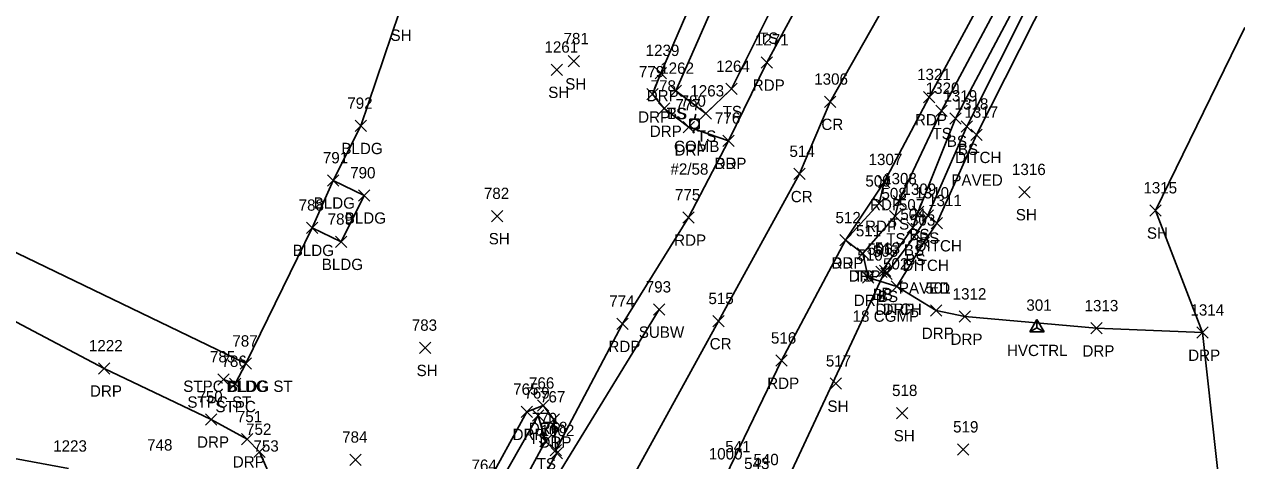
# Model space of a CAD drawing. Extents: x 1639430 to 1640195, y 612006 to 612917.
# Drawn here: x 1639766.2 to 1639980.2, y 612667.5 to 612744.6 of the extents above; entities that cross this region are included whole.
import ezdxf

# ---------------------------------------------------------------- set-up
doc = ezdxf.new("R2010")
doc.units = 0
for name, color, linetype in [('C_A', 7, 'Continuous'), ('C_I', 7, 'Continuous'), ('CPSM', 7, 'Continuous'), ('D_A', 7, 'Continuous'), ('D_C', 7, 'Continuous'), ('D_I', 7, 'Continuous'), ('D_TIC', 7, 'Continuous'), ('DCP', 7, 'Continuous'), ('DD', 7, 'Continuous'), ('L_A', 7, 'Continuous'), ('L_I', 7, 'Continuous'), ('L_TIC', 7, 'Continuous'), ('LABL', 7, 'Continuous'), ('LBC', 7, 'Continuous'), ('LBF', 7, 'Continuous'), ('LELB', 7, 'Continuous'), ('LSOGP', 7, 'Continuous'), ('P_A', 7, 'Continuous'), ('P_I', 7, 'Continuous'), ('P_TIC', 7, 'Continuous'), ('PET', 7, 'Continuous'), ('PRC', 7, 'Continuous'), ('R_A', 7, 'Continuous'), ('R_I', 7, 'Continuous'), ('R_TIC', 7, 'Continuous'), ('RDP', 7, 'Continuous'), ('U_A', 7, 'Continuous'), ('U_C', 7, 'Continuous'), ('U_I', 7, 'Continuous'), ('U_TIC', 7, 'Continuous'), ('UP', 7, 'Continuous'), ('UW', 7, 'Continuous')]:
    doc.layers.add(name, color=color, linetype=linetype)

msp = doc.modelspace()

# ---------------------------------------------------------------- linework, layer by layer
at = {"layer": 'CPSM'}
for p, q in [((1639943.69, 612690.31), (1639944.94, 612692.48)), ((1639943.69, 612690.31), (1639944.94, 612691.03)), ((1639946.19, 612690.31), (1639944.94, 612692.48)), ((1639944.94, 612691.03), (1639944.94, 612692.48)), ((1639944.94, 612691.03), (1639944.94, 612691.03)), ((1639944.94, 612691.03), (1639946.19, 612690.31)), ((1639943.69, 612690.31), (1639946.19, 612690.31))]:
    msp.add_line(p, q, dxfattribs=at)
at = {"layer": 'D_TIC'}
for points in [[(1639933.25, 612724.09), (1639935.25, 612726.09)], [(1639935.25, 612724.09), (1639933.25, 612726.09)], [(1639926.28, 612708.49), (1639928.28, 612710.49)], [(1639928.28, 612708.49), (1639926.28, 612710.49)], [(1639923.98, 612705.05), (1639925.98, 612707.05)], [(1639925.98, 612705.05), (1639923.98, 612707.05)], [(1639917.12, 612700.08), (1639919.12, 612702.08)], [(1639919.12, 612700.08), (1639917.12, 612702.08)], [(1639919.21, 612697.3), (1639921.21, 612699.3)], [(1639921.21, 612697.3), (1639919.21, 612699.3)]]:
    msp.add_lwpolyline(points, dxfattribs=at)
at = {"layer": 'DCP'}
msp.add_lwpolyline([(1639918.12, 612701.08), (1639877.22, 612613.44)], dxfattribs=at)
at = {"layer": 'DD'}
for points in [[(1639927.28, 612709.49), (1639934.25, 612725.09), (1639952.02, 612760.27), (1639969.9, 612794.69), (1639991.51, 612833.72), (1640000.55, 612849.98), (1639999.06, 612851.35), (1640004.27, 612861.49)], [(1639927.28, 612709.49), (1639924.98, 612706.05)], [(1639920.21, 612698.3), (1639924.98, 612706.05)]]:
    msp.add_lwpolyline(points, dxfattribs=at)
at = {"layer": 'L_TIC'}
for points in [[(1639859.2, 612735.58), (1639861.2, 612737.58)], [(1639861.2, 612735.58), (1639859.2, 612737.58)], [(1639862.19, 612737.07), (1639864.19, 612739.07)], [(1639864.19, 612737.07), (1639862.19, 612739.07)], [(1639880.2, 612731.85), (1639882.2, 612733.85)], [(1639882.2, 612731.85), (1639880.2, 612733.85)], [(1639880.2, 612731.85), (1639882.2, 612733.85)], [(1639882.2, 612731.85), (1639880.2, 612733.85)], [(1639890.05, 612732.19), (1639892.05, 612734.19)], [(1639892.05, 612732.19), (1639890.05, 612734.19)], [(1639885.51, 612727.85), (1639887.51, 612729.85)], [(1639887.51, 612727.85), (1639885.51, 612729.85)], [(1639927.08, 612728.31), (1639929.08, 612730.31)], [(1639929.08, 612728.31), (1639927.08, 612730.31)], [(1639929.58, 612726.96), (1639931.58, 612728.96)], [(1639931.58, 612726.96), (1639929.58, 612728.96)], [(1639824.6, 612725.67), (1639826.6, 612727.67)], [(1639826.6, 612725.67), (1639824.6, 612727.67)], [(1639931.54, 612725.53), (1639933.54, 612727.53)], [(1639933.54, 612725.53), (1639931.54, 612727.53)], [(1639819.71, 612716.04), (1639821.71, 612718.04)], [(1639821.71, 612716.04), (1639819.71, 612718.04)], [(1639825.19, 612713.39), (1639827.19, 612715.39)], [(1639827.19, 612713.39), (1639825.19, 612715.39)], [(1639919.56, 612712.35), (1639921.56, 612714.35)], [(1639921.56, 612712.35), (1639919.56, 612714.35)], [(1639941.71, 612713.98), (1639943.71, 612715.98)], [(1639943.71, 612713.98), (1639941.71, 612715.98)], [(1639848.7, 612709.75), (1639850.7, 612711.75)], [(1639850.7, 612709.75), (1639848.7, 612711.75)], [(1639922.98, 612710.48), (1639924.98, 612712.48)], [(1639924.98, 612710.48), (1639922.98, 612712.48)], [(1639924.69, 612709.85), (1639926.69, 612711.85)], [(1639926.69, 612709.85), (1639924.69, 612711.85)], [(1639964.85, 612710.74), (1639966.85, 612712.74)], [(1639966.85, 612710.74), (1639964.85, 612712.74)], [(1639816.01, 612707.68), (1639818.01, 612709.68)], [(1639818.01, 612707.68), (1639816.01, 612709.68)], [(1639918.93, 612709.72), (1639920.93, 612711.72)], [(1639920.93, 612709.72), (1639918.93, 612711.72)], [(1639922.01, 612707.73), (1639924.01, 612709.73)], [(1639924.01, 612707.73), (1639922.01, 612709.73)], [(1639922.27, 612706.07), (1639924.27, 612708.07)], [(1639924.27, 612706.07), (1639922.27, 612708.07)], [(1639821.14, 612705.21), (1639823.14, 612707.21)], [(1639823.14, 612705.21), (1639821.14, 612707.21)], [(1639913.21, 612703.16), (1639915.21, 612705.16)], [(1639915.21, 612703.16), (1639913.21, 612705.16)], [(1639916.5, 612699.9), (1639918.5, 612701.9)], [(1639918.5, 612699.9), (1639916.5, 612701.9)], [(1639917.41, 612699.56), (1639919.41, 612701.56)], [(1639919.41, 612699.56), (1639917.41, 612701.56)], [(1639835.97, 612686.49), (1639837.97, 612688.49)], [(1639837.97, 612686.49), (1639835.97, 612688.49)], [(1639804.32, 612683.7), (1639806.32, 612685.7)], [(1639806.32, 612683.7), (1639804.32, 612685.7)], [(1639804.32, 612683.7), (1639806.32, 612685.7)], [(1639806.32, 612683.7), (1639804.32, 612685.7)], [(1639800.36, 612680.91), (1639802.36, 612682.91)], [(1639802.36, 612680.91), (1639800.36, 612682.91)], [(1639802.45, 612680.12), (1639804.45, 612682.12)], [(1639804.45, 612680.12), (1639802.45, 612682.12)], [(1639908.47, 612680.18), (1639910.47, 612682.18)], [(1639910.47, 612680.18), (1639908.47, 612682.18)], [(1639855.89, 612674.52), (1639857.89, 612676.52)], [(1639857.89, 612674.52), (1639855.89, 612676.52)], [(1639855.89, 612674.52), (1639857.89, 612676.52)], [(1639857.89, 612674.52), (1639855.89, 612676.52)], [(1639920.17, 612674.97), (1639922.17, 612676.97)], [(1639922.17, 612674.97), (1639920.17, 612676.97)], [(1639857.23, 612670.01), (1639859.23, 612672.01)], [(1639859.23, 612670.01), (1639857.23, 612672.01)], [(1639930.94, 612668.54), (1639932.94, 612670.54)], [(1639932.94, 612668.54), (1639930.94, 612670.54)], [(1639823.68, 612666.74), (1639825.68, 612668.74)], [(1639825.68, 612666.74), (1639823.68, 612668.74)]]:
    msp.add_lwpolyline(points, dxfattribs=at)
at = {"layer": 'LABL'}
msp.add_lwpolyline([(1639710.2, 612699.83), (1639711.05, 612687.81), (1639724.43, 612679.59), (1639743.79, 612671.78), (1639774.03, 612666.16)], dxfattribs=at)
at = {"layer": 'LBC'}
for points in [[(1639805.32, 612684.7), (1639817.01, 612708.68), (1639822.14, 612706.21), (1639826.19, 612714.39), (1639820.71, 612717.04), (1639825.6, 612726.67)], [(1639736.37, 612717.97), (1639805.32, 612684.7)]]:
    msp.add_lwpolyline(points, dxfattribs=at)
at = {"layer": 'LBF'}
msp.add_lwpolyline([(1639801.36, 612681.91), (1639803.45, 612681.12), (1639805.32, 612684.7)], dxfattribs=at)
at = {"layer": 'LELB'}
for points in [[(1639881.2, 612732.85), (1639886.51, 612728.85), (1639891.05, 612733.19), (1639897.5, 612746.14), (1639910.14, 612769.99), (1639924.81, 612798.32), (1639936.89, 612820.09), (1639953.99, 612850.42), (1639966.82, 612870.89), (1639970.75, 612884.7)], [(1639920.56, 612713.35), (1639928.08, 612729.31), (1639945.96, 612762.85), (1639965.37, 612798.68), (1639987.12, 612835.84), (1639996.31, 612853.13)], [(1639923.98, 612711.48), (1639930.58, 612727.96), (1639948.36, 612761.64), (1639966.87, 612797.15), (1639988.64, 612835), (1639997.99, 612851.89)], [(1639925.69, 612710.85), (1639932.54, 612726.53), (1639949.92, 612761.12), (1639968.23, 612795.93), (1639988.64, 612835)], [(1639881.2, 612732.85), (1639890.04, 612752.99), (1639899.36, 612776.17), (1639909.23, 612806.8), (1639913.01, 612821.36), (1639914.66, 612832.24)], [(1639920.56, 612713.35), (1639919.93, 612710.72)], [(1639919.93, 612710.72), (1639914.21, 612704.16)], [(1639923.98, 612711.48), (1639923.01, 612708.73)], [(1639925.69, 612710.85), (1639923.27, 612707.07)], [(1639923.27, 612707.07), (1639918.41, 612700.56), (1639917.5, 612700.9), (1639923.01, 612708.73)], [(1639856.89, 612675.52), (1639839.34, 612644.57), (1639837.16, 612635.14)], [(1639856.89, 612675.52), (1639858.23, 612671.01), (1639843.5, 612643.86), (1639837.16, 612635.14)]]:
    msp.add_lwpolyline(points, dxfattribs=at)
at = {"layer": 'LSOGP'}
for points in [[(1639832.37, 612746.66), (1639825.6, 612726.67), (1639820.71, 612717.04), (1639817.01, 612708.68), (1639805.32, 612684.7), (1639736.37, 612717.97), (1639726.62, 612718.64), (1639725.22, 612708.89), (1639710.2, 612699.83), (1639687.52, 612693.83), (1639681.93, 612694.7), (1639686.17, 612669.71), (1639692.76, 612665.5), (1639691.76, 612656.22), (1639684.13, 612637.92), (1639678.27, 612630.17), (1639691.47, 612608.61), (1639716.65, 612607.37), (1639742.63, 612594.56), (1639733.8, 612554.66), (1639717.74, 612525.52)], [(1639984.07, 612643.4), (1639979.17, 612644.84), (1639974.14, 612690.17), (1639965.85, 612711.74), (1639981.6, 612744.05)]]:
    msp.add_lwpolyline(points, dxfattribs=at)
at = {"layer": 'P_TIC'}
for points in [[(1639896.29, 612736.85), (1639898.29, 612738.85)], [(1639898.29, 612736.85), (1639896.29, 612738.85)], [(1639907.46, 612729.93), (1639909.46, 612731.93)], [(1639909.46, 612729.93), (1639907.46, 612731.93)], [(1639924.91, 612730.74), (1639926.91, 612732.74)], [(1639926.91, 612730.74), (1639924.91, 612732.74)], [(1639889.53, 612723.04), (1639891.53, 612725.04)], [(1639891.53, 612723.04), (1639889.53, 612725.04)], [(1639902.06, 612717.18), (1639904.06, 612719.18)], [(1639904.06, 612717.18), (1639902.06, 612719.18)], [(1639917, 612715.74), (1639919, 612717.74)], [(1639919, 612715.74), (1639917, 612717.74)], [(1639916.11, 612711.94), (1639918.11, 612713.94)], [(1639918.11, 612711.94), (1639916.11, 612713.94)], [(1639882.42, 612709.49), (1639884.42, 612711.49)], [(1639884.42, 612709.49), (1639882.42, 612711.49)], [(1639910.17, 612705.47), (1639912.17, 612707.47)], [(1639912.17, 612705.47), (1639910.17, 612707.47)], [(1639870.82, 612690.73), (1639872.82, 612692.73)], [(1639872.82, 612690.73), (1639870.82, 612692.73)], [(1639887.75, 612691.2), (1639889.75, 612693.2)], [(1639889.75, 612691.2), (1639887.75, 612693.2)], [(1639898.84, 612684.23), (1639900.84, 612686.23)], [(1639900.84, 612684.23), (1639898.84, 612686.23)], [(1639859.03, 612668.42), (1639861.03, 612670.42)], [(1639861.03, 612668.42), (1639859.03, 612670.42)], [(1639859.19, 612667.9), (1639861.19, 612669.9)], [(1639861.19, 612667.9), (1639859.19, 612669.9)]]:
    msp.add_lwpolyline(points, dxfattribs=at)
at = {"layer": 'PET'}
for points in [[(1639897.29, 612737.85), (1639913.55, 612767.99), (1639928.75, 612795.82), (1639941.92, 612819.27), (1639957.68, 612846.96), (1639976.9, 612880.46)], [(1639918, 612716.74), (1639925.91, 612731.74), (1639943.29, 612763.86), (1639962.3, 612799.99), (1639983.33, 612836.7), (1639995.21, 612854.18), (1640002.09, 612863.22)], [(1639897.29, 612737.85), (1639890.53, 612724.04)], [(1639860.03, 612669.42), (1639871.82, 612691.73), (1639883.42, 612710.49), (1639890.53, 612724.04)], [(1639918, 612716.74), (1639911.17, 612706.47)], [(1639918, 612716.74), (1639917.11, 612712.94)], [(1639917.11, 612712.94), (1639911.17, 612706.47), (1639899.84, 612685.23)], [(1639899.84, 612685.23), (1639889.96, 612664.78)], [(1639860.03, 612669.42), (1639860.19, 612668.9)], [(1639860.19, 612668.9), (1639846.37, 612644.49), (1639830.05, 612614.56), (1639810.07, 612579.97), (1639792.17, 612548.77), (1639765.87, 612504.14)]]:
    msp.add_lwpolyline(points, dxfattribs=at)
at = {"layer": 'PRC'}
for points in [[(1639988.18, 612868.16), (1639972.03, 612846.35), (1639947.21, 612799.98), (1639926.52, 612762.8), (1639908.46, 612730.93)], [(1639908.46, 612730.93), (1639903.06, 612718.18)], [(1639903.06, 612718.18), (1639888.75, 612692.2)], [(1639888.75, 612692.2), (1639858.8, 612637.72)]]:
    msp.add_lwpolyline(points, dxfattribs=at)
at = {"layer": 'R_TIC'}
for points in [[(1639877.58, 612734.99), (1639879.58, 612736.99)], [(1639879.58, 612734.99), (1639877.58, 612736.99)], [(1639876.07, 612731.23), (1639878.07, 612733.23)], [(1639878.07, 612731.23), (1639876.07, 612733.23)], [(1639878.12, 612728.71), (1639880.12, 612730.71)], [(1639880.12, 612728.71), (1639878.12, 612730.71)], [(1639882.5, 612725.41), (1639884.5, 612727.41)], [(1639884.5, 612725.41), (1639882.5, 612727.41)], [(1639889.53, 612723.04), (1639891.53, 612725.04)], [(1639891.53, 612723.04), (1639889.53, 612725.04)], [(1639910.17, 612705.47), (1639912.17, 612707.47)], [(1639912.17, 612705.47), (1639910.17, 612707.47)], [(1639913.21, 612703.16), (1639915.21, 612705.16)], [(1639915.21, 612703.16), (1639913.21, 612705.16)], [(1639914.13, 612698.87), (1639916.13, 612700.87)], [(1639916.13, 612698.87), (1639914.13, 612700.87)], [(1639919.21, 612697.3), (1639921.21, 612699.3)], [(1639921.21, 612697.3), (1639919.21, 612699.3)], [(1639926.12, 612693.05), (1639928.12, 612695.05)], [(1639928.12, 612693.05), (1639926.12, 612695.05)], [(1639931.19, 612692.01), (1639933.19, 612694.01)], [(1639933.19, 612692.01), (1639931.19, 612694.01)], [(1639954.47, 612689.93), (1639956.47, 612691.93)], [(1639956.47, 612689.93), (1639954.47, 612691.93)], [(1639973.15, 612689.17), (1639975.15, 612691.17)], [(1639975.15, 612689.17), (1639973.15, 612691.17)], [(1639779.33, 612682.86), (1639781.33, 612684.86)], [(1639781.33, 612682.86), (1639779.33, 612684.86)], [(1639856.77, 612676.28), (1639858.77, 612678.28)], [(1639858.77, 612676.28), (1639856.77, 612678.28)], [(1639798.23, 612673.85), (1639800.23, 612675.85)], [(1639800.23, 612673.85), (1639798.23, 612675.85)], [(1639853.91, 612675.19), (1639855.91, 612677.19)], [(1639855.91, 612675.19), (1639853.91, 612677.19)], [(1639858.65, 612673.84), (1639860.65, 612675.84)], [(1639860.65, 612673.84), (1639858.65, 612675.84)], [(1639804.54, 612670.35), (1639806.54, 612672.35)], [(1639806.54, 612670.35), (1639804.54, 612672.35)], [(1639806.73, 612668.12), (1639808.73, 612670.12)], [(1639808.73, 612668.12), (1639806.73, 612670.12)], [(1639859.03, 612668.42), (1639861.03, 612670.42)], [(1639861.03, 612668.42), (1639859.03, 612670.42)]]:
    msp.add_lwpolyline(points, dxfattribs=at)
at = {"layer": 'RDP'}
for points in [[(1639878.58, 612735.99), (1639886.02, 612753.24), (1639899.44, 612786.03), (1639907.89, 612812.69), (1639910.39, 612830.86), (1639909.6, 612844.36), (1639903.5, 612857.59), (1639891.06, 612873.31), (1639887.02, 612878.09)], [(1639878.58, 612735.99), (1639877.07, 612732.23)], [(1639890.53, 612724.04), (1639883.5, 612726.41), (1639879.12, 612729.71), (1639877.07, 612732.23)], [(1639726.62, 612718.64), (1639725.22, 612708.89), (1639753.35, 612698.07), (1639780.33, 612683.86)], [(1639927.12, 612694.05), (1639920.21, 612698.3), (1639915.13, 612699.87), (1639914.21, 612704.16), (1639911.17, 612706.47)], [(1639927.12, 612694.05), (1639932.19, 612693.01)], [(1639932.19, 612693.01), (1639955.47, 612690.93), (1639974.15, 612690.17)], [(1639780.33, 612683.86), (1639799.23, 612674.85)], [(1639825.66, 612646.25), (1639828.33, 612647.84), (1639835.11, 612646.85), (1639838.88, 612647.67), (1639847.56, 612662.76), (1639854.91, 612676.19), (1639857.77, 612677.28), (1639859.65, 612674.84), (1639860.03, 612669.42)], [(1639799.23, 612674.85), (1639805.54, 612671.35), (1639807.73, 612669.12), (1639809.03, 612666.16), (1639809.71, 612655.58), (1639817.32, 612651)]]:
    msp.add_lwpolyline(points, dxfattribs=at)
at = {"layer": 'U_TIC'}
for points in [[(1639877.26, 612693.25), (1639879.26, 612695.25)], [(1639879.26, 612693.25), (1639877.26, 612695.25)]]:
    msp.add_lwpolyline(points, dxfattribs=at)
at = {"layer": 'UP'}
for p, q in [((1639883.66, 612726.21), (1639883.66, 612727.87)), ((1639883.66, 612727.87), (1639885.32, 612727.87)), ((1639884.74, 612728.71), (1639884.49, 612727.87)), ((1639884.49, 612727.04), (1639884.49, 612727.04)), ((1639885.32, 612727.87), (1639885.32, 612726.21)), ((1639885.32, 612726.21), (1639883.66, 612726.21)), ((1639884.24, 612725.37), (1639884.49, 612726.21))]:
    msp.add_line(p, q, dxfattribs=at)
msp.add_circle((1639884.49, 612727.04), 0.833, dxfattribs=at)
at = {"layer": 'UW'}
msp.add_lwpolyline([(1639878.26, 612694.25), (1639853.45, 612653.71), (1639817.16, 612585.63)], dxfattribs=at)

# ---------------------------------------------------------------- texts
at = {"layer": 'C_A'}
msp.add_text('HVCTRL', height=2, dxfattribs=at).set_placement((1639939.64, 612686.03))
at = {"layer": 'C_I'}
msp.add_text('301', height=2, dxfattribs=at).set_placement((1639943.07, 612694.03))
at = {"layer": 'D_A'}
for s, p in [('DITCH', (1639930.49, 612720.09)), ('DITCH', (1639923.51, 612704.49)), ('DITCH', (1639921.21, 612701.05)), ('P', (1639917.49, 612696.08)), ('DITCH', (1639916.44, 612693.3))]:
    msp.add_text(s, height=2, dxfattribs=at).set_placement(p)
at = {"layer": 'D_C'}
for s, p in [('PAVED', (1639929.83, 612716.09)), ('PAVED', (1639920.56, 612697.05)), ('18 CGMP', (1639912.41, 612692.08))]:
    msp.add_text(s, height=2, dxfattribs=at).set_placement(p)
at = {"layer": 'D_I'}
for s, p in [('1317', (1639932.13, 612728.09)), ('1311', (1639925.72, 612712.49)), ('503', (1639922.53, 612709.05)), ('513', (1639916.32, 612704.08)), ('502', (1639917.77, 612701.3))]:
    msp.add_text(s, height=2, dxfattribs=at).set_placement(p)
at = {"layer": 'L_A'}
for s, p in [('SH', (1639830.86, 612741.66)), ('TS', (1639895.91, 612741.14)), ('TS', (1639895.91, 612741.14)), ('SH', (1639858.69, 612731.58)), ('SH', (1639861.68, 612733.07)), ('TS', (1639879.61, 612727.85)), ('BS', (1639879.64, 612727.85)), ('TS', (1639889.46, 612728.19)), ('TS', (1639884.92, 612723.85)), ('TS', (1639926.49, 612724.31)), ('BS', (1639929.02, 612722.96)), ('BLDG', (1639822.19, 612721.67)), ('BS', (1639930.98, 612721.53)), ('BLDG', (1639817.3, 612712.04)), ('SH', (1639941.2, 612709.98)), ('BLDG', (1639822.78, 612709.39)), ('TS', (1639918.97, 612708.35)), ('SH', (1639848.19, 612705.75)), ('TS', (1639918.34, 612705.72)), ('BS', (1639922.42, 612706.48)), ('BS', (1639924.13, 612705.85)), ('SH', (1639964.34, 612706.74)), ('BLDG', (1639813.6, 612703.68)), ('BS', (1639921.45, 612703.73)), ('BLDG', (1639818.73, 612701.21)), ('BS', (1639921.71, 612702.07)), ('TS', (1639912.62, 612699.16)), ('BS', (1639915.94, 612695.9)), ('BS', (1639916.86, 612695.56)), ('SH', (1639835.46, 612682.49)), ('STPC BLDG ST', (1639794.28, 612679.7)), ('BLDG', (1639801.91, 612679.7)), ('STPC ST', (1639795.01, 612676.91)), ('STPC', (1639799.96, 612676.12)), ('SH', (1639907.96, 612676.18)), ('TS', (1639855.3, 612670.52)), ('TS', (1639855.3, 612670.52)), ('SH', (1639919.66, 612670.97)), ('TS', (1639856.64, 612666.01))]:
    msp.add_text(s, height=2, dxfattribs=at).set_placement(p)
at = {"layer": 'L_I'}
for s, p in [('781', (1639861.39, 612741.07)), ('1261', (1639858.02, 612739.58)), ('1262', (1639878.46, 612735.85)), ('1262', (1639878.46, 612735.85)), ('1264', (1639888.31, 612736.19)), ('1263', (1639883.77, 612731.85)), ('1320', (1639925.3, 612732.31)), ('792', (1639823.23, 612729.67)), ('1319', (1639928.44, 612730.96)), ('1318', (1639930.41, 612729.53)), ('791', (1639818.92, 612720.04)), ('790', (1639823.74, 612717.39)), ('1308', (1639917.79, 612716.35)), ('1316', (1639940.53, 612717.98)), ('1309', (1639921.2, 612714.48)), ('1315', (1639963.72, 612714.74)), ('782', (1639847.34, 612713.75)), ('508', (1639917.49, 612713.72)), ('1310', (1639923.47, 612713.85)), ('788', (1639814.65, 612711.68)), ('507', (1639920.57, 612711.73)), ('504', (1639920.83, 612710.07)), ('789', (1639819.77, 612709.21)), ('511', (1639912.98, 612707.16)), ('506', (1639915, 612703.9)), ('505', (1639915.97, 612703.56)), ('783', (1639834.61, 612690.49)), ('787', (1639802.95, 612687.7)), ('787', (1639802.95, 612687.7)), ('785', (1639799, 612684.91)), ('786', (1639801.03, 612684.12)), ('517', (1639907.68, 612684.18)), ('769', (1639854.48, 612678.52)), ('769', (1639854.48, 612678.52)), ('518', (1639919.37, 612678.97)), ('770', (1639855.78, 612674.01)), ('519', (1639930.14, 612672.54)), ('1223', (1639771.33, 612669.16)), ('748', (1639787.91, 612669.35)), ('784', (1639822.32, 612670.74))]:
    msp.add_text(s, height=2, dxfattribs=at).set_placement(p)
at = {"layer": 'P_A'}
for s, p in [('RDP', (1639894.78, 612732.85)), ('CR', (1639906.89, 612725.93)), ('RDP', (1639923.4, 612726.74)), ('RDP', (1639888.02, 612719.04)), ('CR', (1639901.49, 612713.18)), ('RDP', (1639915.48, 612711.74)), ('RDP', (1639914.6, 612707.94)), ('RDP', (1639880.91, 612705.49)), ('RDP', (1639908.66, 612701.47)), ('RDP', (1639869.31, 612686.73)), ('CR', (1639887.18, 612687.2)), ('RDP', (1639897.33, 612680.23))]:
    msp.add_text(s, height=2, dxfattribs=at).set_placement(p)
at = {"layer": 'P_I'}
for s, p in [('1271', (1639895.16, 612740.85)), ('1306', (1639905.63, 612733.93)), ('1321', (1639923.78, 612734.74)), ('776', (1639888.11, 612727.04)), ('514', (1639901.26, 612721.18)), ('1307', (1639915.22, 612719.74)), ('509', (1639914.66, 612715.94)), ('775', (1639881.06, 612713.49)), ('512', (1639909.38, 612709.47)), ('515', (1639886.96, 612695.2)), ('774', (1639869.46, 612694.73)), ('516', (1639897.99, 612688.23)), ('1002', (1639857.34, 612671.9)), ('768', (1639857.62, 612672.42)), ('1000', (1639887.02, 612667.78))]:
    msp.add_text(s, height=2, dxfattribs=at).set_placement(p)
at = {"layer": 'R_A'}
for p in [(1639876.07, 612730.99), (1639874.56, 612727.23), (1639876.61, 612724.71), (1639880.98, 612721.41), (1639888.02, 612719.04), (1639908.66, 612701.47), (1639911.7, 612699.16), (1639912.62, 612694.87), (1639917.7, 612693.3), (1639924.61, 612689.05), (1639929.68, 612688.01), (1639952.96, 612685.93), (1639971.63, 612685.17), (1639777.82, 612678.86), (1639855.26, 612672.28), (1639796.72, 612669.85), (1639852.4, 612671.19), (1639857.14, 612669.84), (1639803.02, 612666.35)]:
    msp.add_text('DRP', height=2, dxfattribs=at).set_placement(p)
at = {"layer": 'R_I'}
for s, p in [('1239', (1639875.88, 612738.99)), ('779', (1639874.7, 612735.23)), ('778', (1639876.76, 612732.71)), ('777', (1639881.13, 612729.41)), ('776', (1639888.11, 612727.04)), ('512', (1639909.38, 612709.47)), ('511', (1639912.98, 612707.16)), ('510', (1639913.25, 612702.87)), ('502', (1639917.77, 612701.3)), ('501', (1639925.25, 612697.05)), ('1312', (1639930.06, 612696.01)), ('1313', (1639953.34, 612693.93)), ('1314', (1639972.02, 612693.17)), ('1222', (1639777.64, 612686.86)), ('766', (1639855.3, 612680.28)), ('750', (1639796.78, 612677.85)), ('765', (1639852.5, 612679.19)), ('767', (1639857.24, 612677.84)), ('751', (1639803.74, 612674.35)), ('752', (1639805.37, 612672.12)), ('768', (1639857.62, 612672.42)), ('753', (1639806.67, 612669.16)), ('541', (1639889.93, 612669.05)), ('764', (1639845.15, 612665.76)), ('543', (1639893.26, 612666.08)), ('540', (1639894.9, 612666.77))]:
    msp.add_text(s, height=2, dxfattribs=at).set_placement(p)
at = {"layer": 'U_A'}
for s, p in [('COMB', (1639880.88, 612722.04)), ('SUBW', (1639874.67, 612689.25))]:
    msp.add_text(s, height=2, dxfattribs=at).set_placement(p)
at = {"layer": 'U_C'}
msp.add_text('#2/58', height=2, dxfattribs=at).set_placement((1639880.26, 612718.04))
at = {"layer": 'U_I'}
for s, p in [('780', (1639882.04, 612730.04)), ('793', (1639875.9, 612697.25))]:
    msp.add_text(s, height=2, dxfattribs=at).set_placement(p)

doc.saveas('drawing.dxf')
